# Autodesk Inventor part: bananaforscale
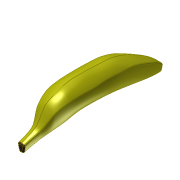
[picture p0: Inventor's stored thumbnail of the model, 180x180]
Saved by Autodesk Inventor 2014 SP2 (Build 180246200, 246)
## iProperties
Created: 2015-03
Part Number: bananaforscale
Material: Generisch
Document SubType Name: Modeling
Designer: Stephan
Density: 1 g/cm^3
Appearance: Gelb
Author: Stephan
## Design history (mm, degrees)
sketch "Skizze1"
  geometry: A1 r 33.471 centre (9.08, -15.456) between (-1.083, 16.435) and (-17.113, 5.384); A2 r 29.406 centre (11.764, -0.172) between (-17.113, 5.384) and (-12.921, -16.153); A3 r 27.967 centre (1.551, 7.778) between (-12.921, -16.153) and (13.616, -17.453); A4 r 25.759 centre (-7.823, -3.174) between (13.616, -17.453) and (14.947, 8.869); A5 r 28.985 centre (-4.848, -12.304) between (14.947, 8.869) and (-1.083, 16.435); 1 further point
  constraints: 10 point on circle, 5 centre point
workplane "Arbeitsebene1"
sketch "Skizze2"
  geometry: A1 r 32.716 centre (1.87, 12.166) between (-12.835, -17.059) and (13.918, -18.25); A2 r 29.769 centre (-11.808, -3.273) between (13.918, -18.25) and (15.759, 7.961); A3 r 29.291 centre (-3.548, -14.067) between (15.759, 7.961) and (-0.722, 15.088); A4 r 24.647 centre (3.189, -9.247) between (-0.722, 15.088) and (-16.263, 5.889); A5 r 28.774 centre (11.493, -1.695) between (-16.263, 5.889) and (-12.835, -17.059); 1 further point
  constraints: 10 point on circle, 5 centre point
workplane "Arbeitsebene2"
sketch "Skizze3"
  geometry: A1 r 37.468 centre (21.108, -0.621) between (-16.043, 4.239) and (-9.943, -21.589); A2 r 24.543 centre (3.404, -10.732) between (-0.436, 13.508) and (-16.043, 4.239); A3 r 34.786 centre (-5.315, -20.935) between (14.855, 7.408) and (-0.436, 13.508); A4 r 37.051 centre (-20.474, -3.756) between (12.003, -21.589) and (14.855, 7.408); A5 r 40.407 centre (1.03, 17.299) between (-9.943, -21.589) and (12.003, -21.589); 1 further point
  constraints: 10 point on circle, 5 centre point
workplane "Arbeitsebene3"
sketch "Skizze4"
  geometry: A1 r 27.48 centre (3.05, -20.549) between (0.734, 6.833) and (-14.13, 0.898); A2 r 42.411 centre (-6.931, -34.879) between (13.847, 2.093) and (0.734, 6.833); A3 r 49.451 centre (-35.084, -5.056) between (9.626, -26.184) and (13.847, 2.093); A4 r 32.689 centre (0.764, 5.28) between (-8.099, -26.184) and (9.626, -26.184); A5 r 43.25 centre (28.87, -3.738) between (-14.13, 0.898) and (-8.099, -26.184); 1 further point
  constraints: 10 point on circle, 5 centre point
workplane "Arbeitsebene4"
sketch "Skizze5"
  geometry: A1 r 30.049 centre (5.206, -32.367) between (-0.359, -2.838) and (-11.541, -7.418); A2 r 23.563 centre (-3.485, -26.192) between (10.753, -7.418) and (-0.359, -2.838); A3 r 53.753 centre (42.191, -8.885) between (-11.541, -7.418) and (-7.232, -30.019); A4 r 16.293 centre (0.031, -15.435) between (-7.232, -30.019) and (7.295, -30.019); A5 r 46.656 centre (-35.689, -11.876) between (7.295, -30.019) and (10.753, -7.418); 1 further point
  constraints: 10 point on circle, 5 centre point
workplane "Arbeitsebene5"
sketch "Skizze6"
  geometry: A1 r 40.723 centre (32.496, -18.422) between (-8.226, -18.065) and (-5.027, -34.246); A2 r 18.726 centre (-0.14, -34.955) between (0, -16.23) and (-8.226, -18.065); A3 r 9.853 centre (-0.872, -26.044) between (5.85, -18.84) and (0, -16.23); A4 r 30.653 centre (-24.534, -22.895) between (3.659, -34.928) and (5.85, -18.84); A5 r 9.824 centre (0.005, -25.809) between (-5.027, -34.246) and (3.659, -34.928); 1 further point
  constraints: 10 point on circle, 5 centre point
workplane "Arbeitsebene6"
sketch "Skizze7"
  geometry: A1 r 6.69 centre (-2.047, -32.527) between (1.687, -26.976) and (-5.088, -26.568); A2 r 44.094 centre (-42.389, -28.217) between (1.114, -35.41) and (1.687, -26.976); A3 r 7.467 centre (-2.047, -28.645) between (-3.22, -36.019) and (1.114, -35.41); A4 r 28.099 centre (23.004, -25.926) between (-5.088, -26.568) and (-3.22, -36.019); 1 further point
  constraints: 8 point on circle, 4 centre point
workplane "Arbeitsebene7"
sketch "Skizze8"
  geometry: A1 r 25.17 centre (3.461, -10.69) between (0, 14.24) and (-16.296, 4.904); A2 r 33.019 centre (16.177, -1.078) between (-16.296, 4.904) and (-12.486, -17.47); A3 r 31.936 centre (2.04, 10.971) between (-12.486, -17.47) and (13.429, -18.865); A4 r 34.478 centre (-17.4, -3.427) between (13.429, -18.865) and (15.361, 7.319); A5 r 24.844 centre (-1.922, -10.53) between (15.361, 7.319) and (0, 14.24); 1 further point
  constraints: 10 point on circle, 5 centre point
workplane "Arbeitsebene8"
sketch "Skizze9"
  geometry: A1 r 49.147 centre (-33.207, -5.107) between (12.288, -23.695) and (14.995, 4.482); A2 r 23.483 centre (-0.616, -13.061) between (14.995, 4.482) and (-1.111, 10.417); A3 r 18.644 centre (-0.45, -8.216) between (-1.111, 10.417) and (-15.572, 2.69); A4 r 51.39 centre (35.72, -0.48) between (-15.572, 2.69) and (-10.589, -22.759); A5 r 24.803 centre (1.749, -1.242) between (-10.589, -22.759) and (12.288, -23.695); 1 further point
  constraints: 10 point on circle, 5 centre point
workplane "Arbeitsebene9"
sketch "Skizze10"
  geometry: A1 r 19.089 centre (0.549, -10.473) between (-7.801, -27.64) and (8.899, -27.64); A2 r 50.01 centre (-37.517, -9.025) between (8.899, -27.64) and (12.217, -3.779); A3 r 20.739 centre (-2.388, -18.503) between (12.217, -3.779) and (0.549, 2.027); A4 r 27.349 centre (4.476, -25.039) between (0.549, 2.027) and (-12.729, -3.779); A5 r 63.245 centre (50.513, -3.157) between (-12.729, -3.779) and (-7.801, -27.64); 1 further point
  constraints: 11 point on circle, 5 centre point
workplane "Arbeitsebene10"
sketch "Skizze11"
  geometry: A1 r 14.555 centre (-1.734, -33.278) between (6.203, -21.078) and (0.502, -18.896); A2 r 26.047 centre (5.161, -44.523) between (0.502, -18.896) and (-6.246, -21.107); A3 r 36.412 centre (30.166, -21.078) between (-6.246, -21.107) and (-3.977, -33.73); A4 r 16.921 centre (-0.341, -17.204) between (-3.977, -33.73) and (3.295, -33.73); A5 r 34.255 centre (-28.031, -19.868) between (3.295, -33.73) and (6.203, -21.078); 1 further point
  constraints: 10 point on circle, 5 centre point
workplane "Arbeitsebene11"
sketch "Skizze12"
  geometry: A1 r 15.094 centre (-0.839, -41.264) between (5.389, -27.514) and (0.1, -26.199); A2 r 29.969 centre (5.842, -55.613) between (0.1, -26.199) and (-4.581, -27.514); A3 r 49.732 centre (45.112, -25.543) between (-4.581, -27.514) and (-2.988, -38.176); A4 r 8.949 centre (-0.288, -29.644) between (-2.988, -38.176) and (2.412, -38.176); A5 r 32.576 centre (-27.019, -24.212) between (2.412, -38.176) and (5.389, -27.514); 1 further point
  constraints: 10 point on circle, 5 centre point
workplane "Arbeitsebene12"
sketch "Skizze13"
  geometry: A1 r 18.226 centre (-2.325, -46.347) between (5.006, -29.661) and (-0.079, -28.26); A2 r 35.125 centre (-29.942, -26.14) between (2.318, -40.033) and (5.006, -29.661); A3 r 13.91 centre (0.16, -26.292) between (-3.133, -39.806) and (2.318, -40.033); A4 r 36.341 centre (31.693, -29.423) between (-4.647, -29.661) and (-3.133, -39.806); A5 r 14.071 centre (1.702, -42.218) between (-0.079, -28.26) and (-4.647, -29.661); 1 further point
  constraints: 10 point on circle, 5 centre point
feature "Erhebung1" sketch "Skizze13" dims "d12" = 0, "d13" = 90 deg, "d14" = 0, "d15" = 90 deg, "d16" = 0, "d17" = 90 deg, "d18" = 0, "d19" = 90 deg, "d20" = 0, "d21" = 90 deg, "d22" = 0, "d23" = 90 deg, "d24" = 0, "d25" = 90 deg, "d26" = 0, "d27" = 90 deg, "d28" = 0, "d29" = 90 deg, "d30" = 0, "d31" = 90 deg, "d32" = 0, "d33" = 90 deg, "d34" = 0, "d35" = 90 deg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
fillet "Rundung1" dims "d38" = 2
fillet "Rundung2" dims "d39" = 2
fillet "Rundung4" dims "d41" = 2
node "Volumenkörper1"
other parameters: "d7" = -15, "d8" = -15, "d9" = -15, "d10" = -15, "d11" = -6.75
